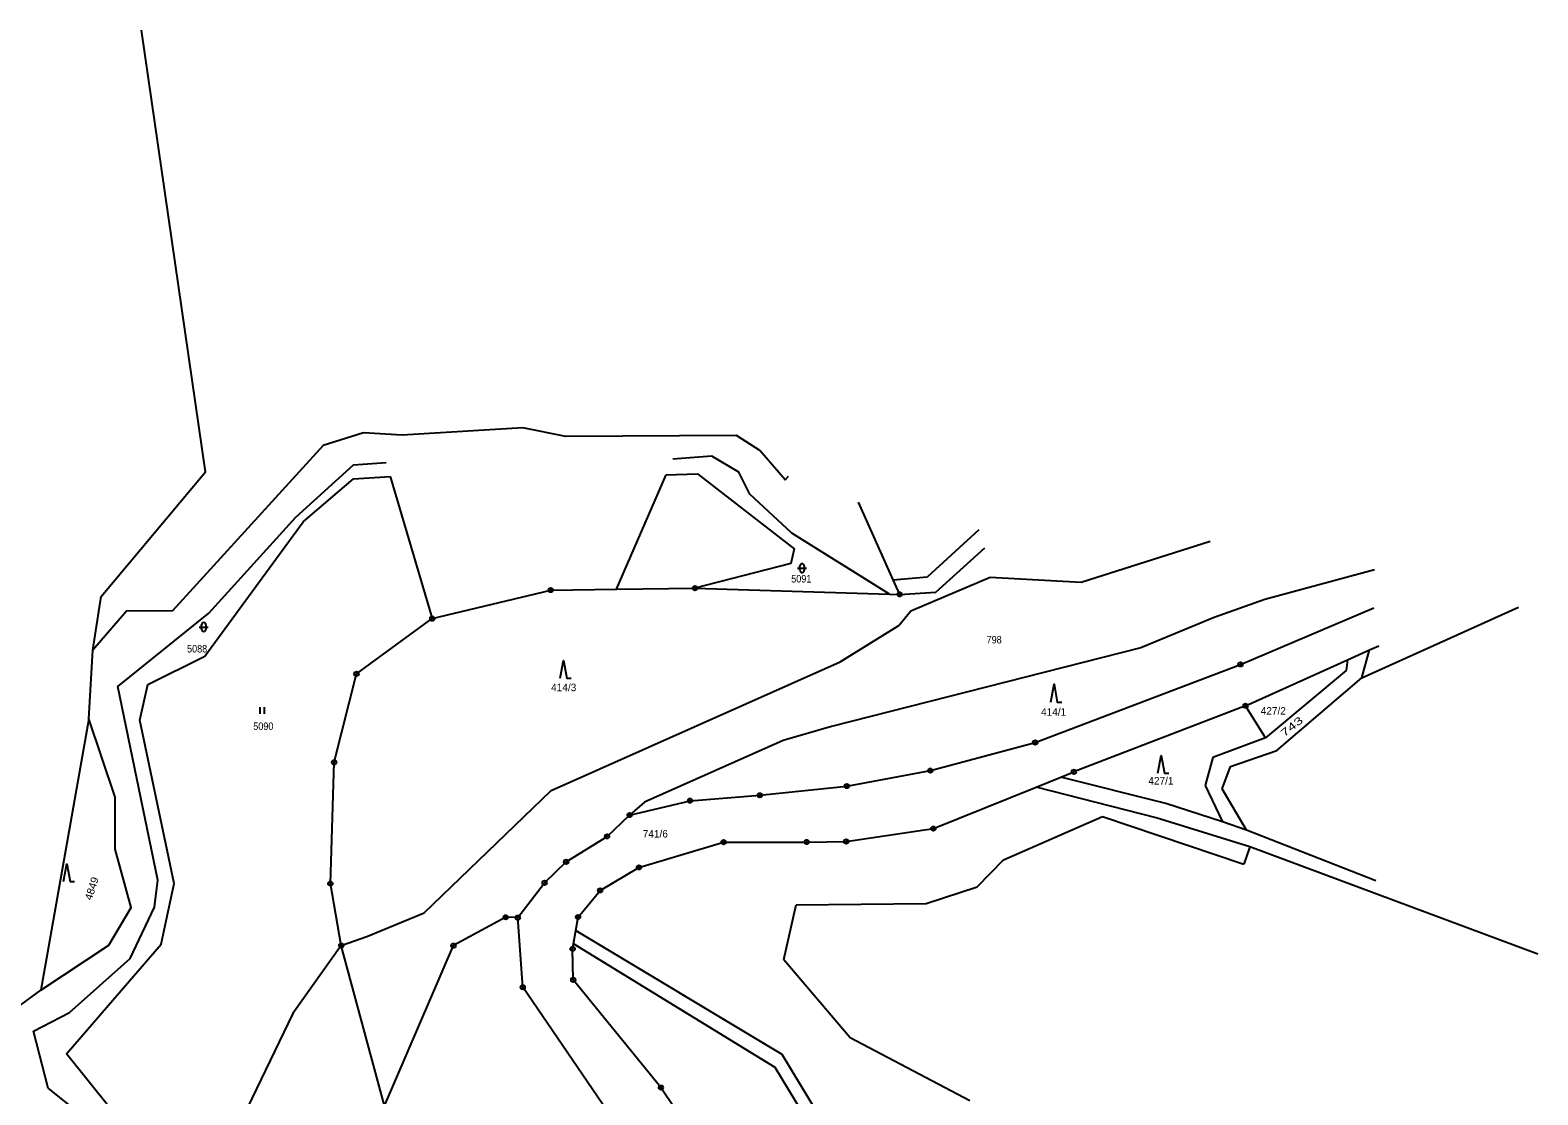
# Model space of a CAD drawing. Extents: x -665688 to -664583, y -1006118 to -1004927.
# Drawn here: x -664932 to -664591.4, y -1005176.4 to -1004935.7 of the extents above; entities that cross this region are included whole.
import ezdxf
from ezdxf.enums import TextEntityAlignment as Align

# ---------------------------------------------------------------- set-up
doc = ezdxf.new("R2010")
doc.units = 0
doc.header["$LTSCALE"] = 0.68
for name, color, linetype, lineweight in [('1', 7, 'Continuous', 25), ('13', 7, 'Continuous', 25), ('24', 7, 'Continuous', 25), ('25', 7, 'Continuous', 25)]:
    doc.layers.add(name, color=color, linetype=linetype, lineweight=lineweight)
doc.layers.add('18', color=7, linetype='Continuous')

msp = doc.modelspace()

# ---------------------------------------------------------------- linework, layer by layer
at = {"layer": '1'}
for p, q in [((-664850.64, -1005036.62), (-664841.17, -1005068.74)), ((-664799.57, -1005062.09), (-664788.33, -1005036.22)), ((-664717.65, -1005048.7), (-664729.29, -1005059.26)), ((-664737.06, -1005059.93), (-664729.29, -1005059.26)), ((-664733, -1005066.95), (-664715.14, -1005059.4)), ((-664735.77, -1005070.32), (-664733, -1005066.95)), ((-664658.54, -1005079.09), (-664628.45, -1005066.28)), ((-664631.13, -1005082.08), (-664595.7, -1005066.12)), ((-664749.02, -1005078.52), (-664735.77, -1005070.32)), ((-664629.39, -1005075.82), (-664627.29, -1005074.88)), ((-664814.33, -1005107.54), (-664749.02, -1005078.52)), ((-664634.39, -1005078.07), (-664634.64, -1005080.45)), ((-664631.13, -1005082.08), (-664629.39, -1005075.82)), ((-664704.93, -1005096.73), (-664658.54, -1005079.09)), ((-664634.64, -1005080.45), (-664652.93, -1005095.68)), ((-664650.32, -1005098.53), (-664631.13, -1005082.08)), ((-664657.4, -1005088.43), (-664696.19, -1005103.35)), ((-664652.93, -1005095.68), (-664657.4, -1005088.43)), ((-664918.73, -1005091.37), (-664929.63, -1005152.7)), ((-664652.93, -1005095.68), (-664664.8, -1005100.15)), ((-664660.78, -1005102.15), (-664650.32, -1005098.53)), ((-664664.8, -1005100.15), (-664666.55, -1005106.44)), ((-664662.7, -1005107.23), (-664660.78, -1005102.15)), ((-664704.68, -1005106.83), (-664699.17, -1005104.57)), ((-664699.17, -1005104.57), (-664696.19, -1005103.35)), ((-664675.38, -1005110.5), (-664699.17, -1005104.57)), ((-664727.94, -1005116.19), (-664704.68, -1005106.83)), ((-664677.62, -1005113.74), (-664704.68, -1005106.83)), ((-664666.55, -1005106.44), (-664662.64, -1005114.69)), ((-664657.16, -1005116.51), (-664662.7, -1005107.23)), ((-664662.64, -1005114.69), (-664675.38, -1005110.5)), ((-664747.63, -1005119.11), (-664727.94, -1005116.19)), ((-664689.69, -1005113.47), (-664657.82, -1005124.19)), ((-664656.46, -1005120.31), (-664677.62, -1005113.74)), ((-664657.16, -1005116.51), (-664662.64, -1005114.69)), ((-664794.46, -1005124.96), (-664775.34, -1005119.25)), ((-664775.34, -1005119.25), (-664756.55, -1005119.22)), ((-664756.55, -1005119.22), (-664747.63, -1005119.11)), ((-664627.97, -1005128), (-664657.16, -1005116.51)), ((-664656.46, -1005120.31), (-664657.82, -1005124.19)), ((-664591.36, -1005144.54), (-664656.46, -1005120.31)), ((-664729.56, -1005133.15), (-664718.04, -1005129.35)), ((-664758.92, -1005133.43), (-664729.56, -1005133.15)), ((-664761.74, -1005145.78), (-664758.92, -1005133.43)), ((-664808.74, -1005139.25), (-664762.2, -1005167.13)), ((-664861.71, -1005142.6), (-664855.97, -1005140.54)), ((-664851.93, -1005178.83), (-664836.36, -1005142.64)), ((-664809.31, -1005150.36), (-664809.44, -1005143.37)), ((-664761.74, -1005145.78), (-664746.72, -1005163.4)), ((-664789.5, -1005174.71), (-664809.31, -1005150.36)), ((-664746.72, -1005163.4), (-664719.7, -1005177.66)), ((-664762.2, -1005167.13), (-664730.44, -1005219.44))]:
    msp.add_line(p, q, dxfattribs=at)
for points in [[(-664917.87, -1005075.84), (-664916, -1005063.77), (-664892.42, -1005035.55), (-664906.83, -1004935.74)], [(-664760.72, -1005036.63), (-664761.42, -1005037.38), (-664767.12, -1005030.72), (-664772.42, -1005027.36), (-664810.96, -1005027.61), (-664820.72, -1005025.63), (-664847.93, -1005027.24), (-664856.66, -1005026.73), (-664865.79, -1005029.64), (-664899.85, -1005066.96), (-664910.21, -1005067.03), (-664917.87, -1005075.84)], [(-664895.39, -1005219.73), (-664908.63, -1005216.84), (-664915.67, -1005184.63), (-664927.97, -1005174.84), (-664931.29, -1005161.96), (-664923.13, -1005157.75), (-664909.4, -1005145.58), (-664903.94, -1005133.92), (-664903.15, -1005127.85), (-664912.19, -1005084.06), (-664891.68, -1005067.49), (-664871.95, -1005045.77), (-664858.98, -1005033.99), (-664851.57, -1005033.48)], [(-664737.86, -1005063.18), (-664759.94, -1005049.43), (-664769.39, -1005040.63), (-664771.9, -1005035.67), (-664778.03, -1005031.99), (-664786.81, -1005032.71)], [(-664894.9, -1005217.74), (-664907.14, -1005211.36), (-664904.2, -1005191.46), (-664923.77, -1005167.11), (-664902.42, -1005142.29), (-664899.45, -1005128.56), (-664907.27, -1005091.69), (-664905.43, -1005083.63), (-664892.51, -1005077.23), (-664870.34, -1005046.85), (-664858.99, -1005037.17), (-664850.64, -1005036.62)], [(-664788.33, -1005036.22), (-664781.25, -1005036.04), (-664759.38, -1005052.97), (-664760.12, -1005056.31), (-664781.81, -1005061.86)], [(-664715.14, -1005059.4), (-664694.54, -1005060.52), (-664665.37, -1005051.2)], [(-664735.57, -1005063.25), (-664727.4, -1005062.79), (-664716.33, -1005052.76)], [(-664628.23, -1005057.7), (-664653.08, -1005064.43), (-664664.49, -1005068.51), (-664681.06, -1005075.36), (-664750.92, -1005093.13), (-664761.85, -1005096.25), (-664793.19, -1005110.19), (-664796.58, -1005113.13)], [(-664929.63, -1005152.7), (-664914.25, -1005142.53), (-664909.2, -1005134.02), (-664912.81, -1005120.81), (-664912.8, -1005109.08), (-664918.73, -1005091.37), (-664917.87, -1005075.84)], [(-664657.4, -1005088.43), (-664634.39, -1005078.07), (-664629.39, -1005075.82)], [(-664767.15, -1005108.65), (-664747.5, -1005106.57), (-664728.61, -1005103.08), (-664704.93, -1005096.73)], [(-664855.97, -1005140.54), (-664843.02, -1005135.26), (-664814.33, -1005107.54)], [(-664821.82, -1005136.31), (-664815.79, -1005128.45), (-664810.91, -1005123.7), (-664801.67, -1005117.95), (-664796.58, -1005113.13), (-664782.91, -1005109.88), (-664767.15, -1005108.65)], [(-664718.04, -1005129.35), (-664712.07, -1005123.24), (-664689.69, -1005113.47)], [(-664808.22, -1005136.18), (-664803.22, -1005130.16), (-664794.46, -1005124.96)], [(-664821.82, -1005136.31), (-664824.56, -1005136.22), (-664836.36, -1005142.64)], [(-664786.99, -1005201.49), (-664820.71, -1005152.05), (-664821.82, -1005136.31)], [(-664809.44, -1005143.37), (-664809.24, -1005142.21), (-664808.74, -1005139.25), (-664808.22, -1005136.18)], [(-664861.71, -1005142.6), (-664872.63, -1005157.96), (-664888.06, -1005189.84), (-664894.9, -1005217.74)], [(-664628.82, -1005305.2), (-664652.8, -1005281.09), (-664689.29, -1005252.19), (-664732.62, -1005221.37), (-664763.66, -1005170.15), (-664809.24, -1005142.21)], [(-664939.22, -1005164.33), (-664937.81, -1005158.74), (-664929.63, -1005152.7)], [(-664789.5, -1005174.71), (-664780.9, -1005187.31), (-664739.22, -1005251.21), (-664703.67, -1005303.61), (-664674.11, -1005348.65)]]:
    msp.add_lwpolyline(points, dxfattribs=at)
at = {"layer": '13'}
for p, q in [((-664744.96, -1005042.39), (-664737.06, -1005059.93)), ((-664737.06, -1005059.93), (-664735.57, -1005063.25)), ((-664841.17, -1005068.74), (-664814.39, -1005062.29)), ((-664814.39, -1005062.29), (-664799.57, -1005062.09)), ((-664799.57, -1005062.09), (-664781.81, -1005061.86)), ((-664781.81, -1005061.86), (-664737.86, -1005063.18)), ((-664737.86, -1005063.18), (-664735.57, -1005063.25)), ((-664858.27, -1005081.21), (-664841.17, -1005068.74)), ((-664863.32, -1005101.21), (-664858.27, -1005081.21)), ((-664864.19, -1005128.62), (-664863.32, -1005101.21)), ((-664861.71, -1005142.6), (-664864.19, -1005128.62)), ((-664851.93, -1005178.83), (-664861.71, -1005142.6))]:
    msp.add_line(p, q, dxfattribs=at)
at = {"layer": '24'}
for centre, radius in [((-664781.81, -1005061.86), 0.5), ((-664814.39, -1005062.29), 0.5), ((-664814.39, -1005062.29), 0.032), ((-664781.81, -1005061.86), 0.032), ((-664735.57, -1005063.25), 0.5), ((-664735.57, -1005063.25), 0.032), ((-664841.17, -1005068.74), 0.5), ((-664841.17, -1005068.74), 0.032), ((-664658.54, -1005079.09), 0.5), ((-664858.27, -1005081.21), 0.5), ((-664858.27, -1005081.21), 0.032), ((-664658.54, -1005079.09), 0.032), ((-664657.4, -1005088.43), 0.5), ((-664657.4, -1005088.43), 0.032), ((-664704.93, -1005096.73), 0.5), ((-664704.93, -1005096.73), 0.032), ((-664863.32, -1005101.21), 0.5), ((-664863.32, -1005101.21), 0.032), ((-664728.61, -1005103.08), 0.5), ((-664728.61, -1005103.08), 0.032), ((-664696.19, -1005103.35), 0.5), ((-664696.19, -1005103.35), 0.032), ((-664782.91, -1005109.88), 0.5), ((-664767.15, -1005108.65), 0.5), ((-664767.15, -1005108.65), 0.032), ((-664747.5, -1005106.57), 0.5), ((-664747.5, -1005106.57), 0.032), ((-664796.58, -1005113.13), 0.5), ((-664782.91, -1005109.88), 0.032), ((-664796.58, -1005113.13), 0.032), ((-664727.94, -1005116.19), 0.5), ((-664727.94, -1005116.19), 0.032), ((-664801.67, -1005117.95), 0.5), ((-664801.67, -1005117.95), 0.032), ((-664775.34, -1005119.25), 0.5), ((-664775.34, -1005119.25), 0.032), ((-664756.55, -1005119.22), 0.5), ((-664756.55, -1005119.22), 0.032), ((-664747.63, -1005119.11), 0.5), ((-664747.63, -1005119.11), 0.032), ((-664810.91, -1005123.7), 0.5), ((-664810.91, -1005123.7), 0.032), ((-664794.46, -1005124.96), 0.5), ((-664794.46, -1005124.96), 0.032), ((-664864.19, -1005128.62), 0.5), ((-664864.19, -1005128.62), 0.032), ((-664815.79, -1005128.45), 0.5), ((-664815.79, -1005128.45), 0.032), ((-664803.22, -1005130.16), 0.5), ((-664803.22, -1005130.16), 0.032), ((-664824.56, -1005136.22), 0.5), ((-664824.56, -1005136.22), 0.032), ((-664821.82, -1005136.31), 0.5), ((-664821.82, -1005136.31), 0.032), ((-664808.22, -1005136.18), 0.5), ((-664808.22, -1005136.18), 0.032), ((-664861.71, -1005142.6), 0.5), ((-664861.71, -1005142.6), 0.032), ((-664836.36, -1005142.64), 0.5), ((-664836.36, -1005142.64), 0.032), ((-664809.44, -1005143.37), 0.5), ((-664809.44, -1005143.37), 0.032), ((-664809.31, -1005150.36), 0.5), ((-664820.71, -1005152.05), 0.5), ((-664820.71, -1005152.05), 0.032), ((-664809.31, -1005150.36), 0.032), ((-664789.5, -1005174.71), 0.5), ((-664789.5, -1005174.71), 0.032)]:
    msp.add_circle(centre, radius, dxfattribs=at)
at = {"layer": '25'}
for p, q in [((-664758.6, -1005057.32), (-664756.6, -1005057.32)), ((-664758.1, -1005057.82), (-664758.1, -1005056.82)), ((-664757.1, -1005056.82), (-664757.1, -1005057.82)), ((-664893.79, -1005070.63), (-664891.79, -1005070.63)), ((-664893.29, -1005071.13), (-664893.29, -1005070.13)), ((-664892.29, -1005070.13), (-664892.29, -1005071.13)), ((-664880.067, -1005090.265), (-664880.067, -1005088.765)), ((-664879.033, -1005090.265), (-664879.033, -1005088.765))]:
    msp.add_line(p, q, dxfattribs=at)
for points in [[(-664812.24, -1005082.22), (-664811.49, -1005078.22), (-664810.74, -1005082.22), (-664809.74, -1005082.22)], [(-664701.43, -1005087.58), (-664700.68, -1005083.58), (-664699.93, -1005087.58), (-664698.93, -1005087.58)], [(-664677.21, -1005103.67), (-664676.46, -1005099.67), (-664675.71, -1005103.67), (-664674.71, -1005103.67)], [(-664924.48, -1005128.16), (-664923.73, -1005124.16), (-664922.98, -1005128.16), (-664921.98, -1005128.16)]]:
    msp.add_lwpolyline(points, dxfattribs=at)
for centre, start, end in [((-664757.6, -1005056.82), 0.101, 180.00143), ((-664757.6, -1005057.82), 180.10243, 0.00286), ((-664892.79, -1005070.13), 0.101, 180.00143), ((-664892.79, -1005071.13), 180.10243, 0.00286)]:
    msp.add_arc(centre, 0.5, start, end, dxfattribs=at)

# ---------------------------------------------------------------- texts
at = {"layer": '18', "width": 0.9}
for s, p in [('5091', (-664757.7795, -1005060.57)), ('5088', (-664894.2895, -1005076.39)), ('798', (-664714.1995, -1005074.34)), ('5090', (-664879.3295, -1005093.9))]:
    msp.add_text(s, height=1.7, dxfattribs=at).set_placement(p, align=Align.CENTER)
at = {"layer": '18'}
for s, p in [('414/3', (-664811.46, -1005085.13)), ('414/1', (-664700.77, -1005090.68)), ('427/2', (-664651.14, -1005090.43)), ('427/1', (-664676.53, -1005106.23)), ('741/6', (-664790.76, -1005118.21))]:
    msp.add_text(s, height=1.7, dxfattribs=at).set_placement(p, align=Align.CENTER)
for s, rotation, width, p in [('743', 39.1, 1.5, (-664646.4371, -1005093.7924)), ('4849', 71.801, 1.05, (-664917.3048, -1005129.992))]:
    msp.add_text(s, height=1.7, rotation=rotation, dxfattribs=dict(at, width=width)).set_placement(p, align=Align.CENTER)

doc.saveas('drawing.dxf')
